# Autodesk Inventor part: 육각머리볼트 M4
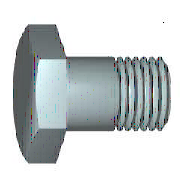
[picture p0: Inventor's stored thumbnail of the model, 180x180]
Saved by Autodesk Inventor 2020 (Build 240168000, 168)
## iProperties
Created: 2012-02
Part Number: 육각머리볼트 M4
Material: 스테인리스강
Description: 6각 머리 볼트 및 6각 머리 나사
Document SubType Name: Modeling
Standard: KS B 1002
Designer: mduedu
Standards Organization: KS
Language: ko-KR
Size Designation: A + B M4 x 10
Categories: <MemberInstance><Categories><Category DisplayName="조임쇠" InternalName="e4da775c-781d-43d5-af7c-5136215cf5a6" Mnemonic="FSTN"><Category DisplayName="볼트" InternalN
Density: 8.08 g/cm^3
Mass: 1.91435 g
Surface Area: 2.70732 cm^2
Volume: 0.236925 cm^3
Appearance: 반광택
IsCustomPart: 1
Author: mduedu
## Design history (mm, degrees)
sketch "스케치1"
  geometry: L1 (0, 2.94)-(0, 2); L2 (2.1, 2)-(10, 2); L3 (10, 2)-(10, 0); L4 (10, 0)-(-0.4, 0); L5 (-2.48, 0)-(12.08, 0) reference; L6 (-0.4, 0)-(-0.4, 2.94); L7 (-0.4, 2.94)-(0, 2.94); L8 (2.1, 2)-(1.67, 2); L9 (1.67, 2)-(0, 2); L10 (0, -0.588)-(0, 3.528) reference
  constraints: 16 end point, 2 collinear, 2 perpendicular, 1 parallel
  dimensions: "d0" = 10 distance between parallel lines of L3 L1 (= NLG); "d1" = 7.9 distance from line of L2.start L3 (= GEL); "d2" = 4 diameter of L2 L4 (= GD); "d9" = 0.4001 distance between parallel lines of L6 L1 (computed from SD); "d10" = 5.88 diameter of L7 L4 (= SD2); "d13" = 0.42952 distance of L2.start L8.end (computed from GAL); "d14" = 4 diameter of L9 L4 (= BDM)
revolve "본체" sketch "스케치1" stored, may be unused: angle "d12" = 90 deg
sketch "스케치2"
  geometry: L1 (0, 4.041)-(3.5, 2.021); L2 (3.5, 2.021)-(3.5, -2.021); L3 (3.5, -2.021)-(0, -4.041); L4 (0, -4.041)-(-3.5, -2.021); L5 (-3.5, -2.021)-(-3.5, 2.021); L6 (-3.5, 2.021)-(0, 4.041); 2 further points
  constraints: 12 end point, 1 coincident, 1 vertical, 11 other
  dimensions: "d11" = 7 distance between parallel lines of L5 L2 (= SW)
extrude "머리" join sketch "스케치2" distance "d3" = 2.4 (= KOH - SD); taper "d4" = 0 deg
sketch "스케치4"
  geometry: L1 (-2.8, 3.5)-(-2.8, 4.041); L2 (-2.8, 4.041)-(-2.487, 4.041); L3 (-2.487, 4.041)-(-2.8, 3.5); L4 (-3.28, 0)-(0.08, 0) reference; L5 (-0.4, 4.041)-(-2.8, 4.041) reference; L6 (-2.8, 2.021)-(-2.8, 4.041) reference
  constraints: 6 end point, 2 collinear, 1 perpendicular, 1 vertical
  dimensions: "d5" = 30 deg angle of L3 L1 (= ANG1); "d19" = 7 diameter of L1.start L4 (= SW0)
revolve "모따기1" sketch "스케치4" stored, may be unused: angle "d21" = 90 deg
workplane "Work Plane1"
body "Solid1"
feature "스레드" dims "d15" = 7.9 (= GEL), "d16" = 0
chamfer "모따기2" distance "d6" = 0.42941 (= -0.5 x SPD + 0.5 x GD); stored, may be unused: second distance "d7" = 0.42952 (computed from GUL), angle "d55" = 45 deg
other parameters: "NLG" = 10 [user parameter; used in 1 equation term], "GD" = 4 (= NND) [user parameter; used in 2 equation terms], "BDM" = 4 (= NND) [user parameter; used in 1 equation term], "KOH" = 2.8 [user parameter; used in 1 equation term], "GEL" = 7.9 [user parameter; used in 2 equation terms], "SW" = 7 [user parameter; used in 3 equation terms], "SW0" = 7 (= SW) [user parameter; used in 1 equation term], "SPD" = 3.14117 (= NND - 1.2269 x PTC) [user parameter; used in 1 equation term], "SD2" = 5.88 (= SDH) [user parameter; used in 1 equation term], "SD" = 0.4 [user parameter; used in 2 equation terms], "ANG1" = 30 deg [user parameter; used in 1 equation term], "GAL" = 0.42941 (= 0.61345 x PTC) [user parameter; used in 1 equation term], "GUL" = 0.42941 (= 0.61345 x PTC) [user parameter; used in 1 equation term], "d8" = 0, "RR" = 0.2 [user parameter], "d57" = 0, "d58" = 0, "TPU" = 14.28571 (computed from PTC) [user parameter], "GD1" = 3.14117 (= THREADDIA - 1.2269 x PTC) [user parameter], "THREADDIA" = 4 [user parameter; used in 1 equation term], "SDH" = 5.88 [user parameter; used in 1 equation term], "SDHG" = 2.1 [user parameter], "TOA" = 30 deg [user parameter], "PTC" = 0.7 [user parameter; used in 5 equation terms], "NND" = 4 [user parameter; used in 3 equation terms], "E0" = 8.085 (= 1.155 x SW) [user parameter]
